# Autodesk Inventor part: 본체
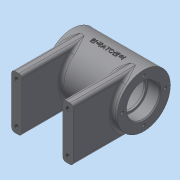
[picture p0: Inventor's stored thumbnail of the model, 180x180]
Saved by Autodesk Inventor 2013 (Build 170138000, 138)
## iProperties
Created: 2020-07
Part Number: 본체
Material: 일반
Document SubType Name: Modeling
Designer: dgall
Density: 1 g/cm^3
Author: dgall
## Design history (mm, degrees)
sketch "스케치1"
  geometry: L1 (-35, 0)-(35, 0); L2 (-35, 0)-(-35, 26); L3 (35, 0)-(35, 26); L4 (35, 26)-(-35, 26); L5 (-35, 16)-(-23.3, 16); L6 (-23, 15.7)-(-23, 14); L7 (-23, 14)-(-21, 14); L8 (-21, 14)-(-21, 18); L9 (-18, 21)-(18, 21); L10 (21, 18)-(21, 14); L11 (21, 14)-(23, 14); L12 (23, 14)-(23, 15.7); L13 (23.3, 16)-(35, 16); A1 r 3 centre (-18, 18) between (-18, 21) and (-21, 18); A2 r 3 centre (18, 18) between (21, 18) and (18, 21); A3 r 0.3 centre (23.3, 15.7) between (23.3, 16) and (23, 15.7); A4 r 0.3 centre (-23.3, 15.7) between (-23, 15.7) and (-23.3, 16); 7 further points
  constraints: 26 end point, 10 point on line, 8 point on circle, 8 tangent, 5 parallel, 5 perpendicular, 4 centre point, 3 collinear, 2 coincident, 2 equal radius, 2 horizontal, 2 horizontal alignment, 2 midpoint
  dimensions: "d0" = 26 distance between parallel lines of L1 L4; "d2" = 21 distance between parallel lines of L1 L9; "d3" = 12 distance of point (23, 16) L13.end; "d4" = 14 distance between parallel lines of L1 L7; "d5" = 70 distance between parallel lines of L3 L2; "d6" = 42 distance of point (-21, 21) point (21, 21); "d7" = 16 distance between parallel lines of L1 L13; "d8" = 3 radius of A1; "d9" = 0.3 radius of A3
revolve "회전1" sketch "스케치1" stored, may be unused: angle "d10" = 90 deg
node "작업 평면1"
sketch "스케치2"
  geometry: L1 (35, 26)-(-35, 26) reference; L2 (35, -26)-(-35, -26) reference; L3 (-30, 26)-(-20, 26); L4 (-20, 26)-(-20, -26); L5 (-20, -26)-(-30, -26); L6 (-30, -26)-(-30, 26); L7 (20, 26)-(30, 26); L8 (30, 26)-(30, -26); L9 (30, -26)-(20, -26); L10 (20, -26)-(20, 26); 1 further point
  constraints: 16 end point, 4 parallel, 4 point on line, 2 horizontal, 2 perpendicular
  dimensions: "d12" = 60 distance between parallel lines of L8 L6; "d14" = 10 distance between parallel lines of L4 L6; "d15" = 10 distance between parallel lines of L10 L8; "d16" = 30 distance from line of L8 point (0, 0)
extrude "돌출1" join sketch "스케치2" stored distance "d17" = 10; taper "d18" = 0 deg
sketch "스케치3"
  geometry: L1 (20, 26)-(30, 26) reference; 3 further points
  constraints: 1 midpoint, 1 vertical alignment
  dimensions: "d19" = 20 vertical distance of point (0, 0) point (25, 20)
hole "구멍1" sketch "스케치3" at (25, 20) diameter "d20" = 4.134; stored, may be unused: countersink angle "d24" = 90 deg, drill point angle "d26" = 118 deg; dims "d21" = 8, "d22" = 4, "d23" = 2, "d25" = 10
fillet "모깎기1" dims "d27" = 3
node "작업 평면2"
sketch "스케치4"
  geometry: C1 r 5 at (0, 0); 1 further point
  constraints: 1 centre point, 1 coincident
  dimensions: "d29" = 10 diameter of C1
extrude "돌출2" join sketch "스케치4" stored distance "d31" = 10; taper "d32" = 0 deg
hole "구멍2" diameter "d35" = 5.188; stored, may be unused: countersink angle "d39" = 90 deg, drill point angle "d41" = 118 deg; dims "d33" = 10, "d34" = 10, "d36" = 8, "d37" = 4, "d38" = 2, "d40" = 10
sketch "스케치5"
  geometry: C1 r 26 at (0, 0) reference; 1 further point
  constraints: 1 vertical alignment
  dimensions: "d42" = 21 distance of C1.centre point (0, 21)
hole "구멍3" sketch "스케치5" at (0, 21) diameter "d43" = 3.242; stored, may be unused: countersink angle "d47" = 90 deg, drill point angle "d49" = 118 deg; dims "d44" = 8, "d45" = 4, "d46" = 2, "d48" = 10
node "작업 평면3"
sketch "스케치6"
  geometry: L1 (-35, -26)-(-35, 26) reference; 2 further points
  constraints: 1 other
  dimensions: "d54" = 35 distance from line of point (0, 0) L1; "d55" = 26 vertical distance of L1.end point (0, 0)
feature "엠보싱1" sketch "스케치6" dims "d0" = 26, "d2" = 21, "d3" = 12, "d4" = 14, "d5" = 70, "d6" = 42, "d7" = 16, "d8" = 3, "d9" = 0.3, "d56" = 0.5, "d57" = 0
chamfer "모따기1" distance "d58" = 1; stored, may be unused: second distance "d59" = 2, angle "d60" = 45 deg
fillet "모깎기2" dims "d61" = 3
fillet "모깎기3" dims "d62" = 2
sketch "스케치7"
  geometry: L1 (0, 0)-(-14.155, 0); L2 (0, 0)-(-27.251, -9.919)
  constraints: 4 end point, 1 horizontal
  dimensions: "d63" = 20 deg angle of L2 L1
node "작업 평면4"
sketch "스케치8"
  geometry: C1 r 6 at (0, 0); 1 further point
  constraints: 1 centre point, 1 coincident
  dimensions: "d64" = 12 diameter of C1
extrude "돌출3" join sketch "스케치8" stored distance "d66" = 10; taper "d67" = 0 deg
hole "구멍4" diameter "d70" = 5.188; stored, may be unused: countersink angle "d74" = 90 deg, drill point angle "d76" = 118 deg; dims "d68" = 10, "d69" = 10, "d71" = 8, "d72" = 4, "d73" = 2, "d75" = 10
fillet "모깎기4" dims "d77" = 2
node "솔리드1"
mirror "대칭1"
mirror "대칭2"
pattern_circular "원형 패턴1" dims angle "d51" = 360 deg
mirror "대칭3"
other parameters: "d11" = -64, "d28" = 29, "d53" = 26
